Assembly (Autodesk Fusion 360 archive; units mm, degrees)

design "Assembly" references "Button", "B2B Connector", "Processor_Cover", "Pins", "USB-C", "LED", "Antenna Connector", "Base"
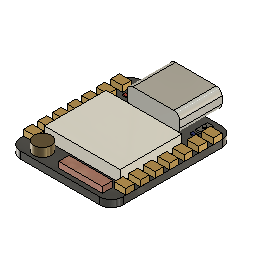
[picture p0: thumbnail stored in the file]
component_insert "Component Insert1"
component_insert "Component Insert2"
joint "Assemble1" alignAngle 0 alignOffsetX 0 alignOffsetY 5 (= "5 mm * Ratio") alignOffsetZ 0
component_insert "Component Insert3"
joint "Assemble2" alignAngle 180 alignOffsetX 0 alignOffsetY 3.8 (= "( 3.8 * Ratio ) * 1 mm") alignOffsetZ 0
component_insert "Component Insert4"
joint "Assemble3" alignAngle 0 alignOffsetX -1 (= "( -1 * Ratio ) * 1 mm") alignOffsetY 0.75 (= "( 0.75 * Ratio ) * 1 mm") alignOffsetZ 0
component_insert "Component Insert5"
joint "Assemble4" alignAngle 0 alignOffsetX -5 (= "( -5 * Ratio ) * 1 mm") alignOffsetY 2 (= "( 2 * Ratio ) * 1 mm") alignOffsetZ 0
component_insert "Component Insert6"
joint "Assemble5" alignAngle 0 alignOffsetX 0 alignOffsetY 0.5 (= "( 0.5 * Ratio ) * 1 mm") alignOffsetZ 0
component_insert "Component Insert7"
joint "Assemble6" alignAngle 0 alignOffsetX 0 alignOffsetY 0.5 (= "( 0.5 * Ratio ) * 1 mm") alignOffsetZ 0
component_insert "Component Insert8"
joint "Assemble7" alignAngle 0 alignOffsetX -0.5 (= "( -0.5 * Ratio ) * 1 mm") alignOffsetY -3.5 (= "( -3.5 * Ratio ) * 1 mm") alignOffsetZ 0
component_insert "Component Insert9"
joint "Assemble8" alignAngle 0 alignOffsetX 0.5 (= "( 0.5 * Ratio ) * 1 mm") alignOffsetY -3.5 (= "( -3.5 * Ratio ) * 1 mm") alignOffsetZ 0
component_insert "Component Insert10"
joint "Assemble9" alignAngle 0 alignOffsetX -0.5 (= "( -0.5 * Ratio ) * 1 mm") alignOffsetY -1 (= "( -1 * Ratio ) * 1 mm") alignOffsetZ 0
component_insert "Component Insert11"
joint "Assemble10" alignAngle 0 alignOffsetX 0.5 (= "( 0.5 * Ratio ) * 1 mm") alignOffsetY -1 (= "( -1 * Ratio ) * 1 mm") alignOffsetZ 0

design "USB-C"
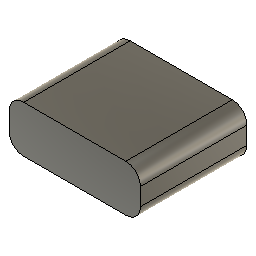
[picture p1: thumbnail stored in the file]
parameter "Ratio" = 1
parameter "fillet" = 1
sketch "Sketch1" plane through (0, 0, 0) normal (0, 0, 1) x axis (1, 0, 0)
  line L1 (-9, 0) -> (0, 0)
  line L2 (-9, 7.3) -> (-9, 0)
  line L3 (0, 7.3) -> (-9, 7.3)
  line L4 (0, 0) -> (0, 7.3)
  point P1 (0, 0)
  point P2 (0, 0)
  point P3 (-9, 0)
  point P5 (0, 7.3)
  horizontal L1
  vertical L2
  horizontal L3
  vertical L4
  coincident P1 P2
  dimension "d1" distance P2 P3 = 9 (= "9 * Ratio")
  dimension "d3" distance P2 P5 = 7.3 (= "7.3 * Ratio")
extrude "Extrude1" new body sketch "Sketch1" along normal blind 3.2 (= "3.2 * Ratio")
fillet "Fillet1" radius 1 (= "fillet")

design "Button"
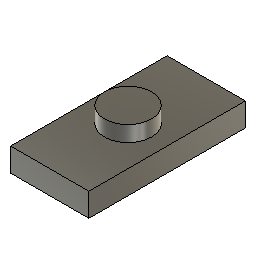
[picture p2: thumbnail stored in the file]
parameter "Hight_Z" = 0.3 (= "0.3 mm * Ratio") comment "for the Base"
parameter "Hight_B" = 0.2 (= "0.2 mm * Ratio") comment "button Hight"
sketch "Sketch1" plane through (0, 0, 0) normal (0, 0, 1) x axis (1, 0, 0)
  line L1 (-1, 0) -> (0, 0)
  line L2 (-1, 2) -> (-1, 0)
  line L3 (0, 2) -> (-1, 2)
  line L4 (0, 0) -> (0, 2)
  point P1 (0, 0)
  point P2 (0, 0)
  point P3 (-1, 0)
  point P5 (0, 2)
  horizontal L1
  vertical L2
  horizontal L3
  vertical L4
  coincident P1 P2
  dimension "d2" distance P2 P3 = 1 (= "( 1 * Ratio ) * 1 mm")
  dimension "d3" distance P2 P5 = 2 (= "( 2 * Ratio ) * 1 mm")
extrude "Extrude1" new body sketch "Sketch1" along normal blind 0.3 (= "Hight_Z")
sketch "Sketch2" plane through (0, 0, 0.3) normal (0, 0, 1) x axis (-1, 0, 0)
  line L1 (1, -2) -> (0, -2)
  line L2 (1, 0) -> (1, -2)
  line L3 (0, 0) -> (1, 0)
  line L4 (0, -2) -> (0, 0)
  circle C1 centre (0.5, -1) radius 0.3
  point P1 (0, 0)
  point P6 (0.5, -1)
  dimension "d8" diameter C1 = 0.6 (= "( 0.6 * Ratio ) * 1 mm")
  dimension "d11" distance P1 P6 = 1 (= "( 1 * Ratio ) * 1 mm")
  dimension "d12" distance P1 P6 = 0.5 (= "( 0.5 * Ratio ) * 1 mm")
extrude "Extrude2" add sketch "Sketch2" profile of C1 along normal blind 0.2 (= "Hight_B")

design "Pins"
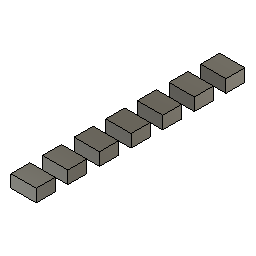
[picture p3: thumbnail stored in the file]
parameter "Hight_Z" = 1
sketch "Sketch1" plane through (0, 0, 0) normal (0, 0, 1) x axis (1, 0, 0)
  line L1 (-2, 0) -> (0, 0)
  line L2 (-2, 1.5) -> (-2, 0)
  line L3 (0, 1.5) -> (-2, 1.5)
  line L4 (0, 0) -> (0, 1.5)
  point P1 (0, 0)
  point P2 (0, 0)
  point P3 (-2, 0)
  point P4 (-2, 1.5)
  horizontal L1
  vertical L2
  horizontal L3
  vertical L4
  coincident P1 P2
  dimension "d2" distance P3 P4 = 1.5 (= "( 1.5 * Ratio ) * 1 mm")
  dimension "d3" distance P2 P3 = 2 (= "( 2 * Ratio ) * 1 mm")
extrude "Extrude1" new body sketch "Sketch1" along normal blind 1 (= "Hight_Z")
rectangular_pattern "R-Pattern1" uSpaceDistance 15 (= "15 mm * Ratio") vSpaceDistance 0

design "LED"
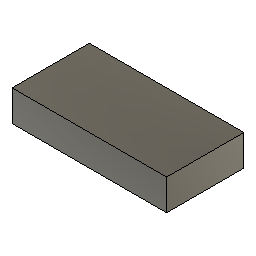
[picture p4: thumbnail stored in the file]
parameter "Hight_Z" = 0.2 (= "0.2 mm * Ratio")
sketch "Sketch1" plane through (0, 0, 0) normal (0, 0, 1) x axis (1, 0, 0)
  line L1 (-1, 0) -> (0, 0)
  line L2 (-1, 0.5) -> (-1, 0)
  line L3 (0, 0.5) -> (-1, 0.5)
  line L4 (0, 0) -> (0, 0.5)
  point P1 (0, 0)
  point P2 (0, 0)
  point P3 (-1, 0)
  point P5 (0, 0.5)
  horizontal L1
  vertical L2
  horizontal L3
  vertical L4
  coincident P1 P2
  dimension "d2" distance P2 P3 = 1 (= "( 1 * Ratio ) * 1 mm")
  dimension "d3" distance P2 P5 = 0.5 (= "( 0.5 * Ratio ) * 1 mm")
extrude "Extrude1" new body sketch "Sketch1" along normal blind 0.2 (= "Hight_Z")

design "Base"
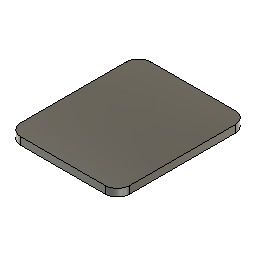
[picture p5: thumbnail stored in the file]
parameter "Lenght_Y" = 21 (= "21 mm * Ratio")
parameter "Lenght_X" = 17.6 (= "17.6 mm * Ratio")
parameter "Fillet" = 2
parameter "Lenght_Z" = 1.2
sketch "Sketch1" plane through (0, 0, 0) normal (0, 0, 1) x axis (1, 0, 0)
  line L1 (-15.6, 0) -> (-2, 0)
  line L2 (-17.6, 19) -> (-17.6, 2)
  line L3 (-2, 21) -> (-15.6, 21)
  line L4 (0, 2) -> (0, 19)
  arc A1 centre (-15.6, 19) radius 2 clockwise from (-17.6, 19) to (-15.6, 21)
  arc A2 centre (-2, 19) radius 2 clockwise from (-2, 21) to (0, 19)
  arc A3 centre (-2, 2) radius 2 clockwise from (0, 2) to (-2, 0)
  arc A4 centre (-15.6, 2) radius 2 clockwise from (-15.6, 0) to (-17.6, 2)
  point P1 (0, 0)
  point P2 (0, 0)
  point P3 (-17.6, 21)
  point P4 (0, 21)
  horizontal L1
  vertical L2
  horizontal L3
  vertical L4
  coincident P1 P2
  coincident P3 L2
  coincident P3 L3
  tangent L2 A1
  tangent L3 A1
  coincident P4 L3
  coincident P4 L4
  tangent L3 A2
  tangent L4 A2
  equal A1 A2
  coincident P2 L1
  coincident P2 L4
  tangent L1 A3
  tangent L4 A3
  equal A1 A3
  tangent L1 A4
  tangent L2 A4
  equal A1 A4
  dimension "d4" distance P3 P4 = 17.6 (= "Lenght_X")
  dimension "d5" distance P2 P4 = 21 (= "Lenght_Y")
  dimension "d7" radius A1 = 2 (= "Fillet")
extrude "Extrude1" new body sketch "Sketch1" along normal blind 1.2 (= "Lenght_Z")

design "B2B Connector"
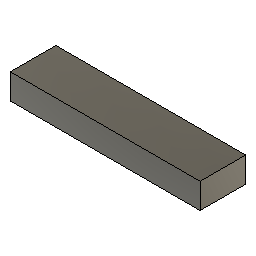
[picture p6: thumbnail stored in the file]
sketch "Sketch1" plane through (0, 0, 0) normal (0, 0, 1) x axis (1, 0, 0)
  line L1 (-7.5, 0) -> (0, 0)
  line L2 (-7.5, 1.8) -> (-7.5, 0)
  line L3 (0, 1.8) -> (-7.5, 1.8)
  line L4 (0, 0) -> (0, 1.8)
  point P1 (0, 0)
  point P2 (0, 0)
  point P5 (0, 1.8)
  point P3 (-7.5, 0)
  horizontal L1
  vertical L2
  horizontal L3
  vertical L4
  coincident P1 P2
  dimension "d2" distance P2 P5 = 1.8 (= "( 1.8 * Ratio ) * 1 mm")
  dimension "d3" distance P2 P3 = 7.5 (= "( 7.5 * Ratio ) * 1 mm")
extrude "Extrude1" new body sketch "Sketch1" along normal blind 1 (= "( 1 * Ratio ) * 1 mm")

design "Antenna Connector"
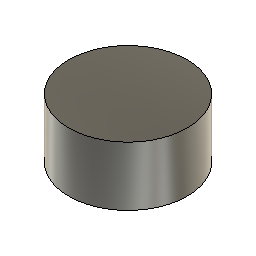
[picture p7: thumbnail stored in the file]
sketch "Sketch1" plane through (0, 0, 0) normal (0, 0, 1) x axis (1, 0, 0)
  circle C1 centre (0, 0) radius 1.5
  point P1 (0, 0)
  point P2 (0, 0)
  coincident P1 P2
  dimension "d2" diameter C1 = 3 (= "( 3 * Ratio ) * 1 mm")
extrude "Extrude1" new body sketch "Sketch1" along normal blind 1.5 (= "( 1.5 * Ratio ) * 1 mm")

design "Processor_Cover"
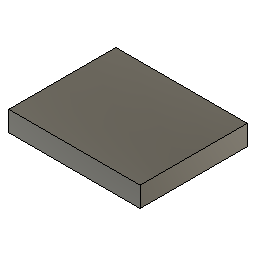
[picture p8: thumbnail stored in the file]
sketch "Sketch1" plane through (0, 0, 0) normal (0, 0, 1) x axis (1, 0, 0)
  line L1 (-13, 0) -> (0, 0)
  line L2 (-13, 10.6) -> (-13, 0)
  line L3 (0, 10.6) -> (-13, 10.6)
  line L4 (0, 0) -> (0, 10.6)
  point P1 (0, 0)
  point P2 (0, 0)
  point P3 (-13, 0)
  point P5 (0, 10.6)
  horizontal L1
  vertical L2
  horizontal L3
  vertical L4
  coincident P1 P2
  dimension "d2" distance P2 P3 = 13 (= "( 13 * Ratio ) * 1 mm")
  dimension "d3" distance P2 P5 = 10.6 (= "( 10.6 * Ratio ) * 1 mm")
extrude "Extrude1" new body sketch "Sketch1" along normal blind 2 (= "( 2 * Ratio ) * 1 mm")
